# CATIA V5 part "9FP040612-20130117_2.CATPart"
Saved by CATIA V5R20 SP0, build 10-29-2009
Part number: 9FP040612-20130117_2
Revision: ANY
Definition: UNKNOWN
Nomenclature: 9FP040612-20130117_2
Source: Unknown
Bounding box of the stored display mesh (mm): x -6 to 6, y -6 to 6, z 0 to 8
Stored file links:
  C:\Users\Utente\Desktop\IO LAVORO\3D X SITO CF\CUMSA\3D files PF\PF 0642WB\9FP040612-20130117_2.CATPart
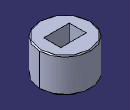
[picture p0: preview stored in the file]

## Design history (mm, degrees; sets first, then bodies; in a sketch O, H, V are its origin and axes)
Body1 "Chaflán1" (main body)
  Solid1: solid without history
